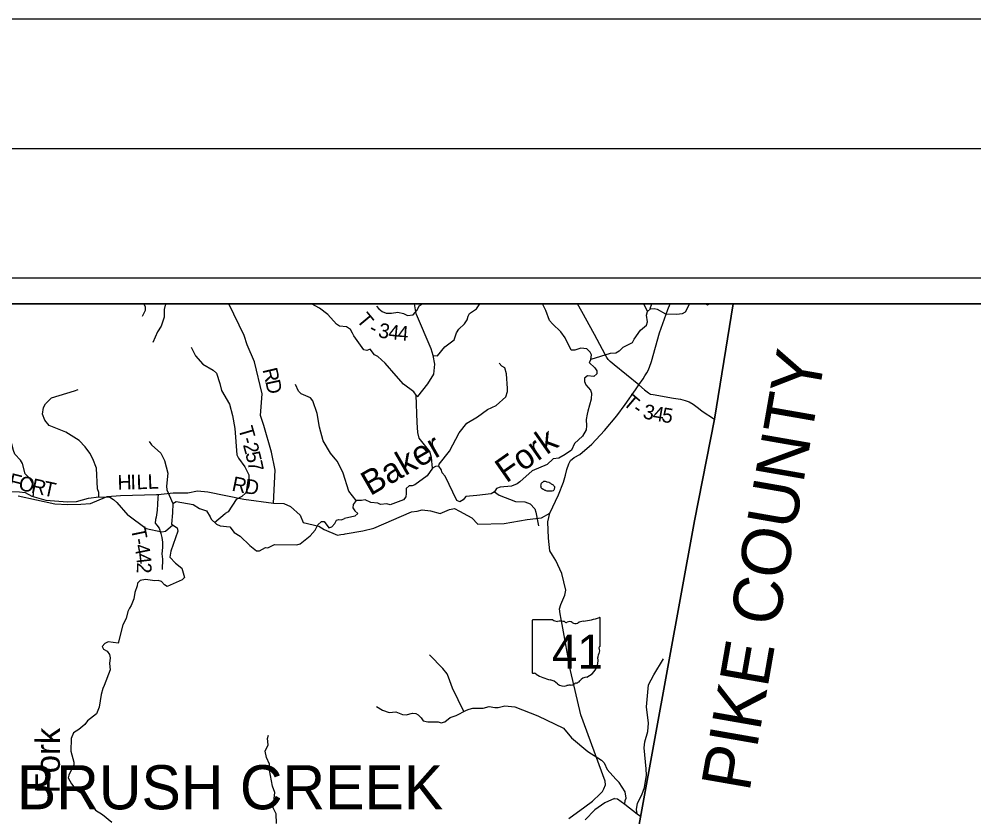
# Model space of a CAD drawing. Extents: x 0 to 34, y 0 to 22.
# Drawn here: x 26.267 to 29.954, y 18.918 to 22 of the extents above; entities that cross this region are included whole.
import ezdxf

# ---------------------------------------------------------------- set-up
doc = ezdxf.new("R2010")
doc.units = 0
for name, color, linetype in [('GM_X_Adjacent_County', 7, 'Continuous'), ('GM_X_Adjacent_County_Text', 7, 'Continuous'), ('GM_X_County', 7, 'Continuous'), ('GM_X_Major_River', 7, 'Continuous'), ('GM_X_Major_River_Text', 7, 'Continuous'), ('GM_X_Minor_Lake', 7, 'Continuous'), ('GM_X_Minor_River', 7, 'Continuous'), ('GM_X_State_Location', 7, 'Continuous'), ('GM_X_State_Route', 7, 'Continuous'), ('GM_X_State_Shield', 7, 'Continuous'), ('GM_X_Township', 7, 'Continuous'), ('GM_X_Township_Road', 7, 'Continuous'), ('GM_X_Township_Road_Text', 7, 'Continuous'), ('GM_X_Township_Text', 7, 'Continuous'), ('SH_Border', 7, 'Continuous'), ('SH_Cut_Line', 7, 'Continuous'), ('SH_Data', 7, 'Continuous')]:
    doc.layers.add(name, color=color, linetype=linetype)

msp = doc.modelspace()

# ---------------------------------------------------------------- linework, layer by layer
at = {"layer": 'GM_X_Adjacent_County'}
for points in [[(29.025, 20.9), (28.9523, 20.4546), (28.8745, 20.061), (28.5665, 18.3656), (28.4154, 17.5565), (28.2182, 16.6548), (28.1843, 16.461), (28.0039, 15.594), (27.9998, 15.5735), (27.9456, 15.2665), (28.3274, 15.217), (28.5345, 15.206), (29.5448, 15.1357), (29.7209, 15.1252), (30.2392, 15.0941), (30.8167, 15.0595)], [(30.8167, 15.0595), (30.8167, 20.9), (29.025, 20.9)]]:
    msp.add_lwpolyline(points, dxfattribs=at)
at = {"layer": 'GM_X_County'}
for points in [[(29.025, 20.9), (24.0167, 20.9), (24.0167, 14.5214)], [(24.0167, 14.5214), (24.6978, 14.628), (24.8262, 14.6485), (26.4085, 14.9262), (26.4461, 14.9325), (27.6234, 15.1875), (27.9456, 15.2665), (27.9998, 15.5735), (28.0039, 15.594), (28.1843, 16.461), (28.2182, 16.6548), (28.4154, 17.5565), (28.5665, 18.3656), (28.8745, 20.061), (28.9523, 20.4546), (29.025, 20.9)]]:
    msp.add_lwpolyline(points, dxfattribs=at)
at = {"layer": 'GM_X_Major_River'}
for points in [[(28.5836, 20.7168), (28.5713, 20.7087), (28.5489, 20.7079), (28.4744, 20.6853), (28.4678, 20.6737), (28.4902, 20.6531), (28.4979, 20.6416), (28.4977, 20.6291), (28.4869, 20.6194), (28.4615, 20.6214), (28.4507, 20.6124), (28.4504, 20.5999), (28.4555, 20.5873), (28.473, 20.5661), (28.4777, 20.5542), (28.4757, 20.5314), (28.4638, 20.4853), (28.4602, 20.4732), (28.4572, 20.4535), (28.4586, 20.4284), (28.4564, 20.4129), (28.4431, 20.3892), (28.4114, 20.3597), (28.4006, 20.3341), (28.376, 20.3182), (28.3518, 20.3038), (28.3298, 20.3008), (28.3058, 20.2788), (28.248, 20.2548), (28.2001, 20.2116), (28.1901, 20.2049), (28.1683, 20.1958), (28.1246, 20.192), (28.1108, 20.1869), (28.1033, 20.1742), (28.0903, 20.1657), (28.0343, 20.1591), (27.9914, 20.1557), (27.9816, 20.1429), (27.9689, 20.1348), (27.9573, 20.1403), (27.9124, 20.2346), (27.9012, 20.247), (27.8965, 20.2603), (27.8872, 20.2723), (27.8747, 20.2721), (27.8632, 20.2644), (27.8421, 20.2351), (27.7948, 20.201), (27.7848, 20.1966), (27.7727, 20.1968), (27.7618, 20.1864), (27.762, 20.1769), (27.7622, 20.1674), (27.7605, 20.1541), (27.7508, 20.1433), (27.6995, 20.1237), (27.6867, 20.1277), (27.6623, 20.1251), (27.6518, 20.1299), (27.6253, 20.1319), (27.6027, 20.1433), (27.5897, 20.1405), (27.5688, 20.1401), (27.5572, 20.1247), (27.5558, 20.1122), (27.5635, 20.1003), (27.5747, 20.0902), (27.5628, 20.0802), (27.5238, 20.0705)], [(26.8609, 20.1289), (26.8737, 20.1361), (26.9386, 20.1252), (26.9641, 20.1088), (26.9906, 20.1), (27.0048, 20.0772)], [(26.8609, 20.1289), (26.8598, 20.0925)], [(26.8598, 20.0925), (26.8551, 20.0487), (26.8776, 20.0348), (26.8794, 20.0219), (26.8529, 19.9441), (26.8485, 19.921), (26.8702, 19.8977), (26.895, 19.8785), (26.9052, 19.8431), (26.8968, 19.833), (26.8391, 19.8085), (26.8278, 19.8147), (26.8169, 19.8269), (26.8037, 19.8309), (26.7908, 19.8298), (26.7546, 19.8355), (26.7341, 19.8315), (26.7245, 19.8206), (26.7233, 19.81), (26.7136, 19.7847), (26.7103, 19.7605), (26.6991, 19.7341), (26.6929, 19.7239), (26.6867, 19.7107), (26.6804, 19.6839), (26.6677, 19.6593), (26.6496, 19.5894), (26.6103, 19.5936), (26.5974, 19.588), (26.5882, 19.576), (26.593, 19.5657), (26.6065, 19.558), (26.6162, 19.5446), (26.6191, 19.5325), (26.6155, 19.5101), (26.6179, 19.4855), (26.5954, 19.425), (26.5907, 19.4137), (26.5833, 19.391), (26.5764, 19.3414), (26.5659, 19.3158), (26.5305, 19.2885), (26.5209, 19.2753), (26.4972, 19.2554), (26.4774, 19.2431), (26.4674, 19.2205), (26.4669, 19.1723), (26.4778, 19.1298), (26.4784, 19.1172), (26.4638, 19.0912), (26.4584, 19.0788), (26.4568, 19.0689), (26.4686, 19.0449), (26.4873, 19.022), (26.5121, 19.0066), (26.5618, 18.9432), (26.5889, 18.9266), (26.6246, 18.8971)], [(27.0048, 20.0772), (27.0081, 20.0676), (27.0295, 20.0481), (27.0427, 20.0427), (27.0805, 20.0389), (27.098, 20.0163), (27.1202, 20.0021), (27.1584, 19.9665), (27.1836, 19.9457), (27.1949, 19.9452), (27.2178, 19.9579), (27.2276, 19.9578), (27.2531, 19.9704), (27.3393, 19.9685), (27.3526, 19.9725), (27.3904, 20.004), (27.4103, 20.0261), (27.4203, 20.0465), (27.4352, 20.0585), (27.4454, 20.0584), (27.4626, 20.0351), (27.4743, 20.0384), (27.4862, 20.0519), (27.492, 20.064), (27.5015, 20.0669), (27.5113, 20.0649), (27.5238, 20.0705)]]:
    msp.add_lwpolyline(points, dxfattribs=at)
at = {"layer": 'GM_X_Minor_Lake'}
for points in [[(28.2925, 20.2133), (28.2898, 20.2114), (28.2875, 20.2098), (28.2853, 20.2079), (28.283, 20.2057), (28.2822, 20.2034), (28.2815, 20.1996), (28.2807, 20.1973), (28.2811, 20.1954), (28.2811, 20.1935), (28.2815, 20.1905), (28.283, 20.1886), (28.2853, 20.1871), (28.2871, 20.1859), (28.289, 20.184), (28.2917, 20.1833), (28.294, 20.1818), (28.2966, 20.1802), (28.2993, 20.1795), (28.3015, 20.1787), (28.3053, 20.178), (28.3076, 20.1776), (28.314, 20.1776), (28.3159, 20.178), (28.3182, 20.1776), (28.3205, 20.178), (28.3228, 20.1772), (28.325, 20.1772), (28.33, 20.1787), (28.3319, 20.1802), (28.3334, 20.1821), (28.3345, 20.184), (28.3349, 20.1859), (28.3353, 20.189), (28.3353, 20.1924), (28.3338, 20.1947), (28.3319, 20.1966), (28.33, 20.1992), (28.3254, 20.2023), (28.3228, 20.2038), (28.3205, 20.2057), (28.3175, 20.2072), (28.3156, 20.2079), (28.3133, 20.2091), (28.3065, 20.2114), (28.3038, 20.2117), (28.3, 20.2129), (28.2978, 20.2136), (28.2925, 20.2133)], [(28.2925, 20.2133), (28.2898, 20.2114), (28.2875, 20.2098), (28.2853, 20.2079), (28.283, 20.2057), (28.2822, 20.2034), (28.2815, 20.1996), (28.2807, 20.1973), (28.2811, 20.1954), (28.2811, 20.1935), (28.2815, 20.1905), (28.283, 20.1886), (28.2853, 20.1871), (28.2871, 20.1859), (28.289, 20.184), (28.2917, 20.1833), (28.294, 20.1818), (28.2966, 20.1802), (28.2993, 20.1795), (28.3015, 20.1787), (28.3053, 20.178), (28.3076, 20.1776), (28.314, 20.1776), (28.3159, 20.178), (28.3182, 20.1776)], [(28.3182, 20.1776), (28.3205, 20.178), (28.3228, 20.1772), (28.325, 20.1772), (28.33, 20.1787), (28.3319, 20.1802), (28.3334, 20.1821), (28.3345, 20.184), (28.3349, 20.1859), (28.3353, 20.189), (28.3353, 20.1924), (28.3338, 20.1947), (28.3319, 20.1966), (28.33, 20.1992), (28.3254, 20.2023), (28.3228, 20.2038), (28.3205, 20.2057), (28.3175, 20.2072), (28.3156, 20.2079), (28.3133, 20.2091), (28.3065, 20.2114), (28.3038, 20.2117), (28.3, 20.2129), (28.2978, 20.2136), (28.2925, 20.2133)]]:
    msp.add_lwpolyline(points, dxfattribs=at)
at = {"layer": 'GM_X_Minor_River'}
for points in [[(26.7483, 20.9), (26.7536, 20.8884), (26.7538, 20.874), (26.7416, 20.8514)], [(26.8376, 20.9), (26.8309, 20.8954), (26.8267, 20.878), (26.8277, 20.8487), (26.8149, 20.8133), (26.8016, 20.7915), (26.7833, 20.7511)], [(27.8632, 20.2644), (27.859, 20.3066), (27.8526, 20.3299), (27.8118, 20.3808), (27.8065, 20.4022), (27.8046, 20.4421), (27.7998, 20.547), (27.7913, 20.5597), (27.7516, 20.5893), (27.723, 20.6221), (27.681, 20.6704), (27.6518, 20.6964), (27.6387, 20.7034), (27.6227, 20.725), (27.6094, 20.7195), (27.5976, 20.7228), (27.5595, 20.7763), (27.554, 20.7866), (27.5471, 20.8008), (27.5313, 20.8106), (27.5048, 20.8134), (27.4932, 20.8219), (27.4597, 20.8582), (27.4275, 20.8828), (27.3956, 20.9)], [(27.7998, 20.547), (27.8069, 20.542), (27.8454, 20.5903), (27.8685, 20.6279), (27.8719, 20.6666), (27.866, 20.6997), (27.8586, 20.7257), (27.8015, 20.8589), (27.7994, 20.8692), (27.7932, 20.9)], [(27.866, 20.6997), (27.8831, 20.699), (27.9115, 20.7342), (27.9465, 20.7606), (27.9558, 20.7885), (27.9644, 20.802), (27.9872, 20.8229), (27.9966, 20.8379), (28.0007, 20.8523), (28.0058, 20.8621), (28.0331, 20.8802), (28.0463, 20.9)], [(28.4744, 20.6853), (28.4771, 20.7035), (28.4723, 20.7135), (28.4589, 20.7266), (28.4361, 20.7282), (28.4128, 20.7206), (28.3992, 20.7205), (28.375, 20.7692), (28.3595, 20.7923), (28.3263, 20.8225), (28.3155, 20.836), (28.3014, 20.8739), (28.2881, 20.9)], [(28.5836, 20.7168), (28.599, 20.7327), (28.6361, 20.7501), (28.6423, 20.7637), (28.6667, 20.7976), (28.6898, 20.8171), (28.6934, 20.8303), (28.6896, 20.8566), (28.6939, 20.8698), (28.7058, 20.8803), (28.7188, 20.882), (28.7305, 20.8792), (28.7625, 20.8614), (28.8057, 20.8597), (28.8282, 20.8624), (28.8404, 20.8691), (28.8541, 20.8963), (28.8564, 20.9)], [(28.6785, 20.9), (28.6939, 20.8698)], [(28.7058, 20.8803), (28.704, 20.8825), (28.7105, 20.9)], [(28.9178, 20.9), (28.9251, 20.8965), (28.9305, 20.9)], [(26.9311, 20.7321), (26.9479, 20.6984), (26.9769, 20.6663), (27.0167, 20.644), (27.0294, 20.632), (27.0423, 20.5918), (27.0487, 20.5651), (27.0796, 20.5129), (27.0913, 20.469), (27.0998, 20.4183), (27.1074, 20.3163), (27.114, 20.3033), (27.1392, 20.2706), (27.1534, 20.2388), (27.1554, 20.2061), (27.1533, 20.1917), (27.1411, 20.1679), (27.1268, 20.1553), (27.1057, 20.1446), (27.0748, 20.0958), (27.0629, 20.0896)], [(27.8872, 20.2723), (27.8889, 20.2802), (27.9286, 20.3304), (27.9667, 20.4012), (27.9959, 20.4394), (28.037, 20.4637), (28.0759, 20.4915), (28.1096, 20.5073), (28.1467, 20.5408), (28.1528, 20.5608), (28.153, 20.573), (28.1487, 20.6293), (28.1431, 20.6522), (28.1311, 20.6592), (28.1203, 20.6708)], [(26.3161, 20.1573), (26.3219, 20.1599), (26.3222, 20.1952), (26.3186, 20.209), (26.3102, 20.2232), (26.2897, 20.2429), (26.2805, 20.2834), (26.2728, 20.2957), (26.2508, 20.3185), (26.2446, 20.333), (26.2153, 20.4456), (26.1812, 20.4922), (26.1599, 20.5314), (26.148, 20.5817)], [(27.5688, 20.1401), (27.5403, 20.1767), (27.5188, 20.2459), (27.4969, 20.2907), (27.4872, 20.3015), (27.469, 20.3235), (27.4414, 20.3711), (27.4268, 20.4231), (27.4176, 20.4764), (27.4018, 20.5249), (27.3921, 20.5365), (27.3567, 20.5516), (27.3459, 20.5628), (27.3346, 20.5877)], [(26.5743, 20.1546), (26.5742, 20.1709), (26.5692, 20.1847), (26.5661, 20.2645), (26.552, 20.3017), (26.5395, 20.3235), (26.5221, 20.3474), (26.4986, 20.3714), (26.4472, 20.4042), (26.3824, 20.4297), (26.3657, 20.4501), (26.357, 20.4742), (26.3606, 20.4996), (26.3684, 20.5132), (26.3916, 20.5367), (26.481, 20.5643), (26.4944, 20.5686)], [(26.7697, 20.3676), (26.7785, 20.3549), (26.8148, 20.3228), (26.8287, 20.2948), (26.8406, 20.2452), (26.8359, 20.1951), (26.8372, 20.181), (26.8609, 20.1289)], [(26.2109, 20.1763), (26.2682, 20.1738), (26.2902, 20.1715), (26.3161, 20.1573), (26.3698, 20.1416), (26.4536, 20.1351), (26.4881, 20.1364), (26.5351, 20.1488), (26.5743, 20.1546), (26.6168, 20.1535), (26.631, 20.1441), (26.6437, 20.1324), (26.6869, 20.083)], [(28.1033, 20.1742), (28.1209, 20.1605), (28.1839, 20.1359), (28.2199, 20.1348), (28.2399, 20.1276), (28.2585, 20.1075), (28.2628, 20.0945), (28.2727, 20.0422)], [(26.8606, 20.0453), (26.8325, 20.0209), (26.8184, 20.0176), (26.7573, 20.0311), (26.6869, 20.083)], [(27.0215, 20.0554), (27.0629, 20.0896)], [(27.9849, 19.325), (27.9399, 19.4151), (27.9256, 19.4581), (27.9193, 19.4707), (27.9028, 19.4905), (27.8523, 19.5441)], [(28.6543, 18.9296), (28.6508, 18.9469), (28.655, 18.9707), (28.6722, 19.0035), (28.6825, 19.0314), (28.6893, 19.0784), (28.6889, 19.1035), (28.6803, 19.1852), (28.6833, 19.2072), (28.6949, 19.2472), (28.6973, 19.2798), (28.6896, 19.3433), (28.6977, 19.4282), (28.7177, 19.4666), (28.755, 19.5279)], [(27.6471, 19.3449), (27.6708, 19.3302), (27.6965, 19.3209), (27.7222, 19.3236), (27.7475, 19.3132), (27.7622, 19.3119), (27.7857, 19.3185), (27.7986, 19.3172), (27.8084, 19.3126), (27.8196, 19.3011), (27.8278, 19.2885), (27.8448, 19.2845), (27.8849, 19.2856), (27.8974, 19.2817), (27.911, 19.285), (27.9316, 19.3019), (27.9551, 19.3092), (27.9943, 19.33), (28.0053, 19.3337), (28.0194, 19.3378), (28.0591, 19.3377), (28.0822, 19.3443), (28.1045, 19.3407), (28.117, 19.3406), (28.1428, 19.3464), (28.181, 19.3434), (28.2707, 19.308), (28.3693, 19.2611), (28.4007, 19.2229), (28.463, 19.1704), (28.516, 19.1368), (28.5262, 19.1261), (28.5376, 19.1014), (28.5481, 19.0891), (28.5725, 19.0619)], [(27.2605, 18.8923), (27.2594, 18.9291), (27.2479, 18.9523), (27.2549, 19.0117), (27.2449, 19.0369), (27.2342, 19.0988), (27.2347, 19.109), (27.2333, 19.1215), (27.2218, 19.1474), (27.2175, 19.1713), (27.2287, 19.1962), (27.2263, 19.2205), (27.2299, 19.2338)], [(28.6056, 18.9664), (28.6078, 18.9813), (28.6116, 18.99), (28.6074, 19.0147), (28.5841, 19.0507), (28.5725, 19.0619)], [(28.5657, 18.9892), (28.5778, 18.9875), (28.6056, 18.9664)], [(28.5666, 18.989), (28.5288, 18.9722), (28.4899, 18.9445), (28.4525, 18.9059)], [(28.6056, 18.9664), (28.6543, 18.9296)], [(28.6543, 18.9296), (28.666, 18.9211)]]:
    msp.add_lwpolyline(points, dxfattribs=at)
at = {"layer": 'GM_X_State_Route'}
for points in [[(28.3901, 18.9121), (28.4512, 18.9569), (28.4814, 18.9782), (28.5113, 19.0074), (28.5201, 19.0153), (28.5248, 19.0259), (28.5314, 19.0421), (28.5305, 19.0562), (28.4357, 19.3125), (28.3968, 19.4827), (28.3644, 19.6609), (28.3558, 19.702), (28.3537, 19.7218), (28.3589, 19.7388), (28.3737, 19.7747), (28.3788, 19.7932), (28.3633, 19.8587), (28.3396, 19.9084), (28.3262, 19.9294), (28.3158, 19.9455), (28.3107, 19.995), (28.3084, 20.0576), (28.3164, 20.0906), (28.3495, 20.1616), (28.3695, 20.211), (28.3769, 20.2378), (28.3824, 20.2605), (28.3893, 20.2817), (28.3956, 20.2941), (28.4107, 20.3056), (28.4322, 20.3184), (28.479, 20.3578), (28.528, 20.4111), (28.5752, 20.4668), (28.6067, 20.5105), (28.6473, 20.5674), (28.6599, 20.5869), (28.6762, 20.61), (28.6831, 20.6214), (28.6912, 20.6332), (28.6961, 20.6429), (28.7009, 20.6547), (28.7095, 20.6774), (28.74, 20.7882), (28.7727, 20.8784), (28.7812, 20.9)], [(28.6599, 20.5869), (28.5645, 20.664), (28.5499, 20.6766), (28.5422, 20.6852), (28.5367, 20.6931), (28.5306, 20.7038), (28.4884, 20.7818), (28.44, 20.8703), (28.4237, 20.9)]]:
    msp.add_lwpolyline(points, dxfattribs=at)
at = {"layer": 'GM_X_State_Shield'}
for p, q in [((28.2476, 19.6761), (28.2476, 19.476)), ((28.3274, 19.6795), (28.2502, 19.6795)), ((28.5112, 19.5798), (28.5112, 19.6845)), ((28.5112, 19.5798), (28.5112, 19.5798))]:
    msp.add_line(p, q, dxfattribs=at)
for centre, radius, start, end in [((28.2506, 19.6765), 0.00305, 98.1301, 188.1301), ((28.3458, 19.7028), 0.0296, 231.6195, 271.1119), ((28.3556, 19.5672), 0.1064, 80.4867, 94.9883), ((28.3797, 19.6775), 0.00855, 219.7921, 297.1024), ((28.3923, 19.6544), 0.0178, 54.4667, 119.1411), ((28.4152, 19.6861), 0.0214, 233.8562, 294.8282), ((28.453, 19.6184), 0.0563, 97.3462, 120.7689), ((28.4173, 19.9524), 0.2796, 275.8445, 288.9065), ((28.5083, 19.6849), 0.00294, 351.8621, 97.738), ((28.5081, 19.5794), 0.00314, 289.6038, 7.7341), ((28.5218, 19.536), 0.0198, 136.8065, 186.9296), ((28.5106, 19.5721), 0.00454, 107.944, 210.337), ((28.4817, 19.5589), 0.0273, 340.033, 23.6496), ((28.433, 19.5227), 0.0699, 292.3089, 8.9858), ((28.2506, 19.4755), 0.00308, 171.9584, 258.3066), ((28.2511, 19.496), 0.0235, 267.339, 280.6039), ((28.2559, 19.4644), 0.00848, 29.7484, 93.2717), ((28.363, 19.6442), 0.2019, 240.4129, 257.1985), ((28.3028, 19.3861), 0.0632, 47.1842, 75.836), ((28.3711, 19.4634), 0.0401, 230.7004, 286.2918), ((28.3972, 19.4484), 0.0214, 268.777, 315.5493), ((28.4165, 19.4291), 0.00601, 65.7517, 132.6484), ((28.4139, 19.4566), 0.0226, 282.8732, 323.2771), ((28.4625, 19.4198), 0.0383, 94.4031, 142.5768), ((28.3943, 19.3942), 0.0329, 85.6951, 111.2099)]:
    msp.add_arc(centre, radius, start, end, dxfattribs=at)
at = {"layer": 'GM_X_Township'}
for points in [[(29.025, 20.9), (24.0167, 20.9), (24.0167, 14.5214)], [(24.0167, 14.5214), (24.6978, 14.628), (24.8262, 14.6485), (26.4085, 14.9262), (26.4461, 14.9325), (27.6234, 15.1875), (27.9456, 15.2665), (27.9998, 15.5735), (28.0039, 15.594), (28.1843, 16.461), (28.2182, 16.6548), (28.4154, 17.5565), (28.5665, 18.3656), (28.8745, 20.061), (28.9523, 20.4546), (29.025, 20.9)]]:
    msp.add_lwpolyline(points, dxfattribs=at)
at = {"layer": 'GM_X_Township_Road'}
for points in [[(27.2493, 20.1299), (27.2554, 20.2567), (27.2419, 20.3274), (27.2117, 20.4303), (27.1997, 20.4682), (27.2059, 20.5525), (27.1755, 20.6763), (27.1475, 20.742), (27.1354, 20.7776), (27.0771, 20.9)], [(27.6474, 20.8915), (27.6565, 20.88), (27.6684, 20.8698), (27.6838, 20.8638), (27.7046, 20.8633), (27.729, 20.8672), (27.7517, 20.8622), (27.767, 20.8549), (27.7887, 20.8571), (27.8032, 20.8746), (27.8131, 20.893), (27.8238, 20.9)], [(28.6599, 20.5869), (28.6823, 20.5682), (28.6977, 20.5556), (28.705, 20.5515), (28.7156, 20.5491), (28.7939, 20.5361), (28.8211, 20.5312), (28.839, 20.5268), (28.8548, 20.5207), (28.8695, 20.5118), (28.8902, 20.4971), (28.9047, 20.4857), (28.9523, 20.4546)], [(26.2632, 20.1579), (26.4051, 20.1268), (26.4551, 20.1249), (26.5049, 20.1256), (26.5425, 20.1289), (26.5766, 20.1433), (26.6065, 20.1551), (26.6582, 20.16), (26.7975, 20.1627), (26.8039, 20.1634), (26.8622, 20.1699), (26.9183, 20.1694), (26.9557, 20.178), (26.9958, 20.1732), (27.1347, 20.1448), (27.2493, 20.1299), (27.2891, 20.1279), (27.3143, 20.1174), (27.3522, 20.0834), (27.3633, 20.0546), (27.4245, 20.0405), (27.445, 20.0284), (27.4969, 20.0065), (27.5094, 20.0083)], [(26.8039, 20.1634), (26.8022, 20.1504), (26.801, 20.1265), (26.8006, 20.1026), (26.7964, 20.0756), (26.7933, 20.0672), (26.7929, 20.0524), (26.7982, 20.0448), (26.8073, 20.0334), (26.8144, 20.0132), (26.8182, 19.9969), (26.8212, 19.9794), (26.8212, 19.9642), (26.8206, 19.9583)], [(27.5094, 20.0083), (27.5224, 20.0103), (27.5265, 20.0109), (27.5947, 20.0225), (27.6369, 20.033), (27.7816, 20.0965), (27.8046, 20.0992), (27.8231, 20.1045), (27.856, 20.0999), (27.8926, 20.0903), (27.929, 20.1058), (27.9481, 20.1088), (27.9675, 20.0988), (27.9986, 20.0821), (28.0147, 20.0726), (28.0386, 20.0484), (28.1401, 20.051), (28.2284, 20.0669), (28.2841, 20.0734), (28.3164, 20.0906)], [(26.8206, 19.9583), (26.8206, 19.9579), (26.8185, 19.9346), (26.8207, 19.9129), (26.8195, 19.8734)]]:
    msp.add_lwpolyline(points, dxfattribs=at)
at = {"layer": 'SH_Border'}
msp.add_lwpolyline([(2, 21.5), (33.5, 21.5), (33.5, 0.5), (2, 0.5)], close=True, dxfattribs=at)
at = {"layer": 'SH_Cut_Line'}
msp.add_lwpolyline([(0, 0), (34, 0), (34, 22), (0, 22)], close=True, dxfattribs=at)
at = {"layer": 'SH_Data'}
for points in [[(23.9167, 21), (30.9167, 21), (30.9167, 14), (23.9167, 14)], [(24.0167, 20.9), (30.8167, 20.9), (30.8167, 14.1), (24.0167, 14.1)]]:
    msp.add_lwpolyline(points, close=True, dxfattribs=at)

# ---------------------------------------------------------------- texts
at = {"layer": 'GM_X_Adjacent_County_Text'}
msp.add_text('PIKE COUNTY', height=0.189394, rotation=80.0952, dxfattribs=at).set_placement((29.0866, 19.0106))
at = {"layer": 'GM_X_Major_River_Text'}
for s, height, rotation, p in [('Fork', 0.0947, 35.0018, (28.1483, 20.2057)), ('Baker', 0.0947, 30.0015, (27.623, 20.1564)), ('Fork', 0.09471, 89.5778, (26.4235, 19.0087))]:
    msp.add_text(s, height=height, rotation=rotation, dxfattribs=at).set_placement(p)
at = {"layer": 'GM_X_State_Location'}
msp.add_text('41', height=0.000189, rotation=0, dxfattribs=at).set_placement((28.6523, 20.7419))
for s in ['s', 'r']:
    msp.add_text(s, height=0.000189, dxfattribs=at).set_placement((28.7, 20.7557))
at = {"layer": 'GM_X_State_Shield'}
msp.add_text('41', height=0.13184, dxfattribs=at).set_placement((28.3247, 19.4901))
at = {"layer": 'GM_X_Township_Road_Text'}
for s, rotation, p in [('T', 309.6497, (27.5671, 20.8365)), ('-', 332.5137, (27.6133, 20.7884)), ('3', 348.7973, (27.6505, 20.7718)), ('4', 353.8387, (27.6903, 20.7642)), ('4', 355.471, (27.7268, 20.7603)), ('R', 283.2591, (27.2066, 20.6459)), ('D', 282.2044, (27.2173, 20.6008)), ('T', 319.5716, (28.5956, 20.5134)), ('-', 323.905, (28.6316, 20.483)), ('3', 346.667, (28.6726, 20.459)), ('4', 350.7022, (28.711, 20.4501)), ('5', 350.7328, (28.7456, 20.4444)), ('T', 286.0884, (27.1126, 20.4185)), ('2', 285.3692, (27.1307, 20.3554)), ('-', 285.9261, (27.1244, 20.3777)), ('5', 284.2546, (27.1399, 20.3219)), ('7', 282.0682, (27.1484, 20.2885)), ('F', 345.996, (26.2229, 20.1916)), ('O', 347.2641, (26.2615, 20.182)), ('R', 347.7674, (26.3108, 20.1709)), ('T', 347.7766, (26.3564, 20.161)), ('H', 1.5338, (26.6476, 20.1815)), ('I', 1.5302, (26.6976, 20.1828)), ('L', 1.5548, (26.7209, 20.1834)), ('L', 2.4434, (26.7644, 20.1846)), ('R', 348.4275, (27.0855, 20.1785)), ('D', 352.005, (27.135, 20.1684)), ('T', 281.3847, (26.6982, 20.0313)), ('-', 281.3696, (26.7066, 19.9897)), ('4', 281.2293, (26.7112, 19.9668)), ('4', 276.6764, (26.7178, 19.9337)), ('2', 269.4432, (26.7218, 19.9008))]:
    msp.add_text(s, height=0.0568, rotation=rotation, dxfattribs=at).set_placement(p)
at = {"layer": 'GM_X_Township_Text'}
msp.add_text('BRUSH CREEK', height=0.170455, rotation=0, dxfattribs=at).set_placement((26.2582, 18.947))

doc.saveas('drawing.dxf')
